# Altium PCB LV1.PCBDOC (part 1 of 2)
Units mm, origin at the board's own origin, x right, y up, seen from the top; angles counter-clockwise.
Board outline 220.06 x 100 mm, 2 copper layers (Component Side, Bottom Layer), stack 0.325 mm thick; 185 components, 114 nets, 661 pads, 212 vias.
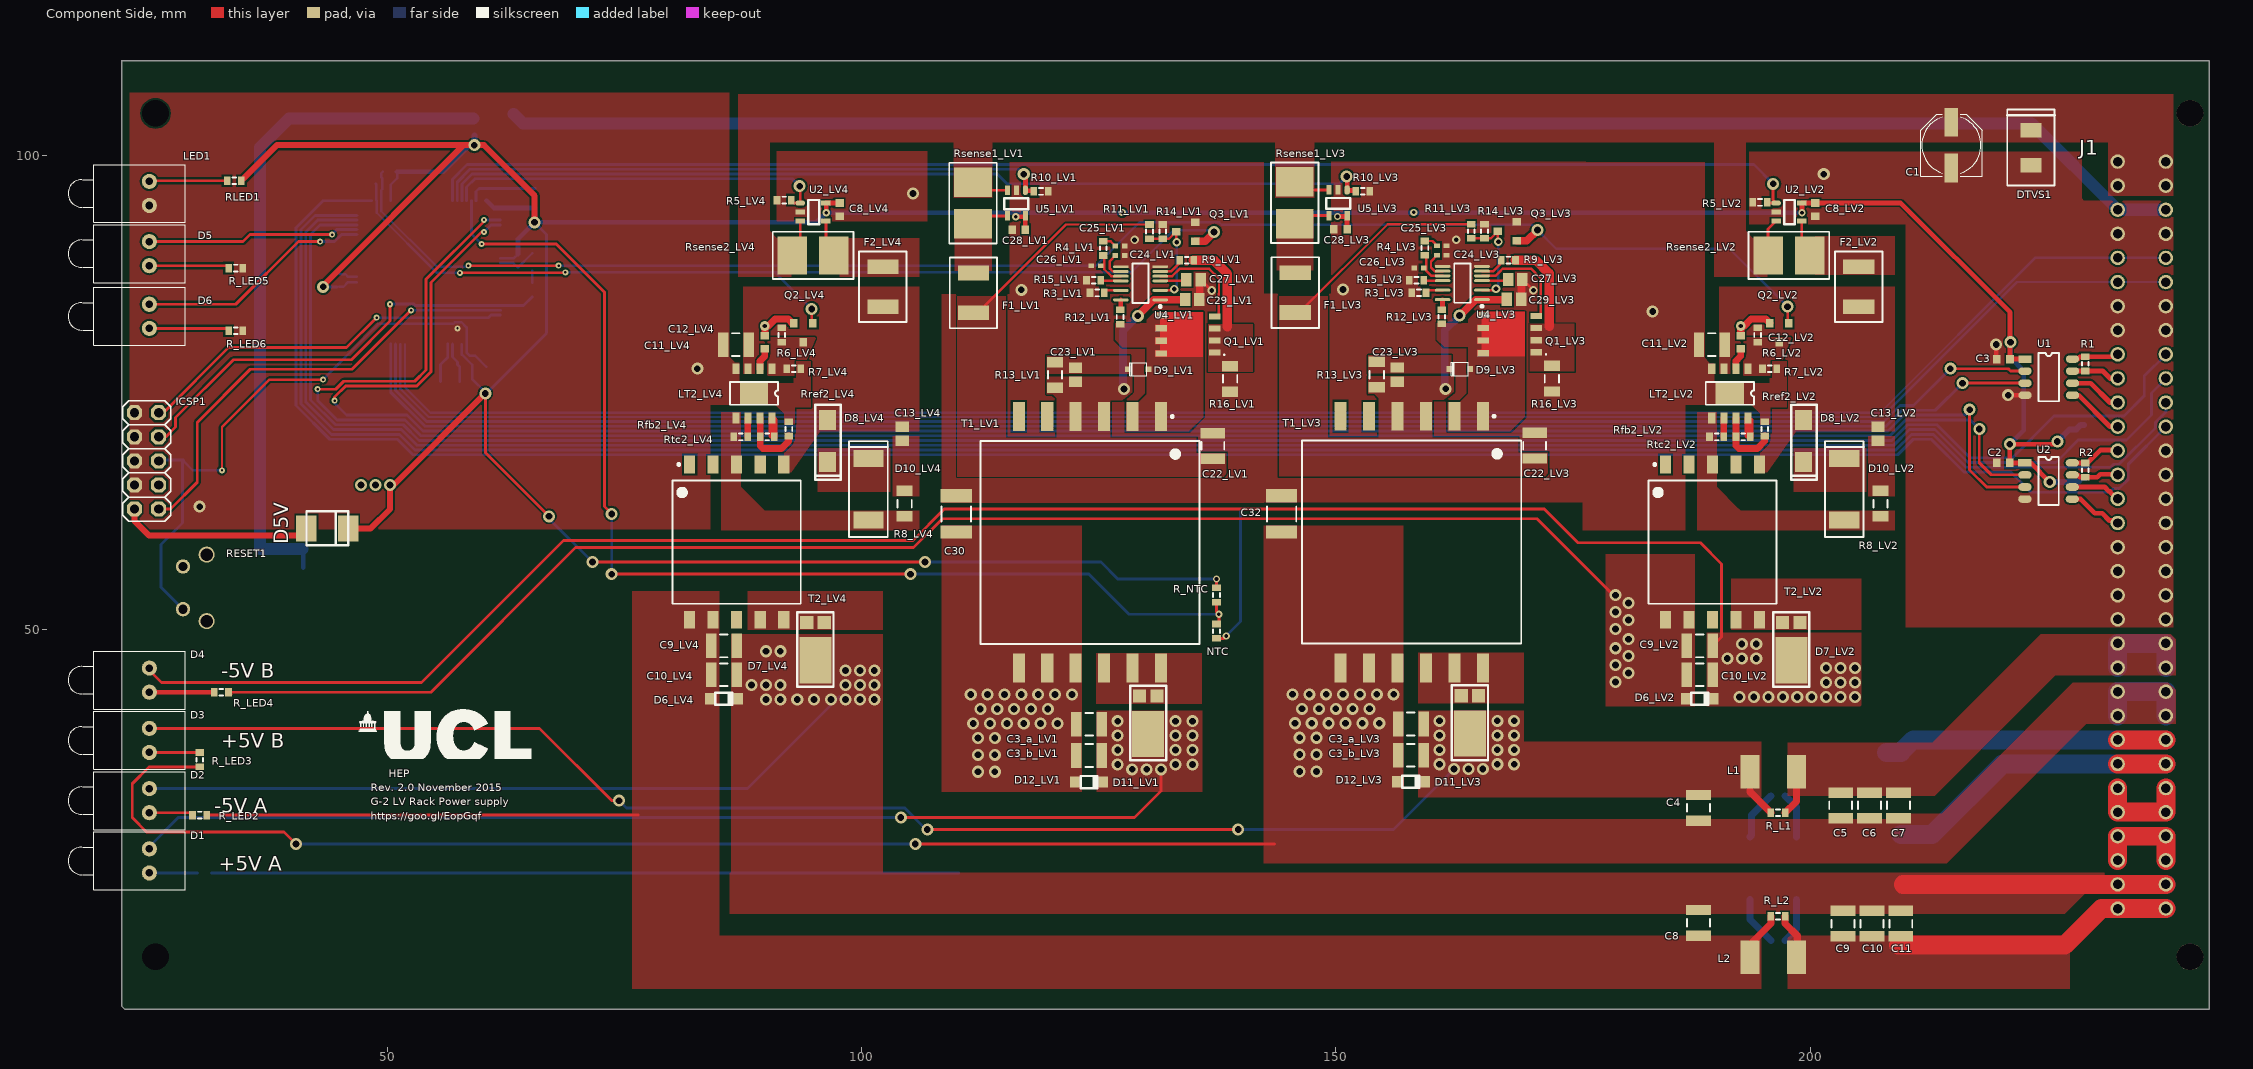
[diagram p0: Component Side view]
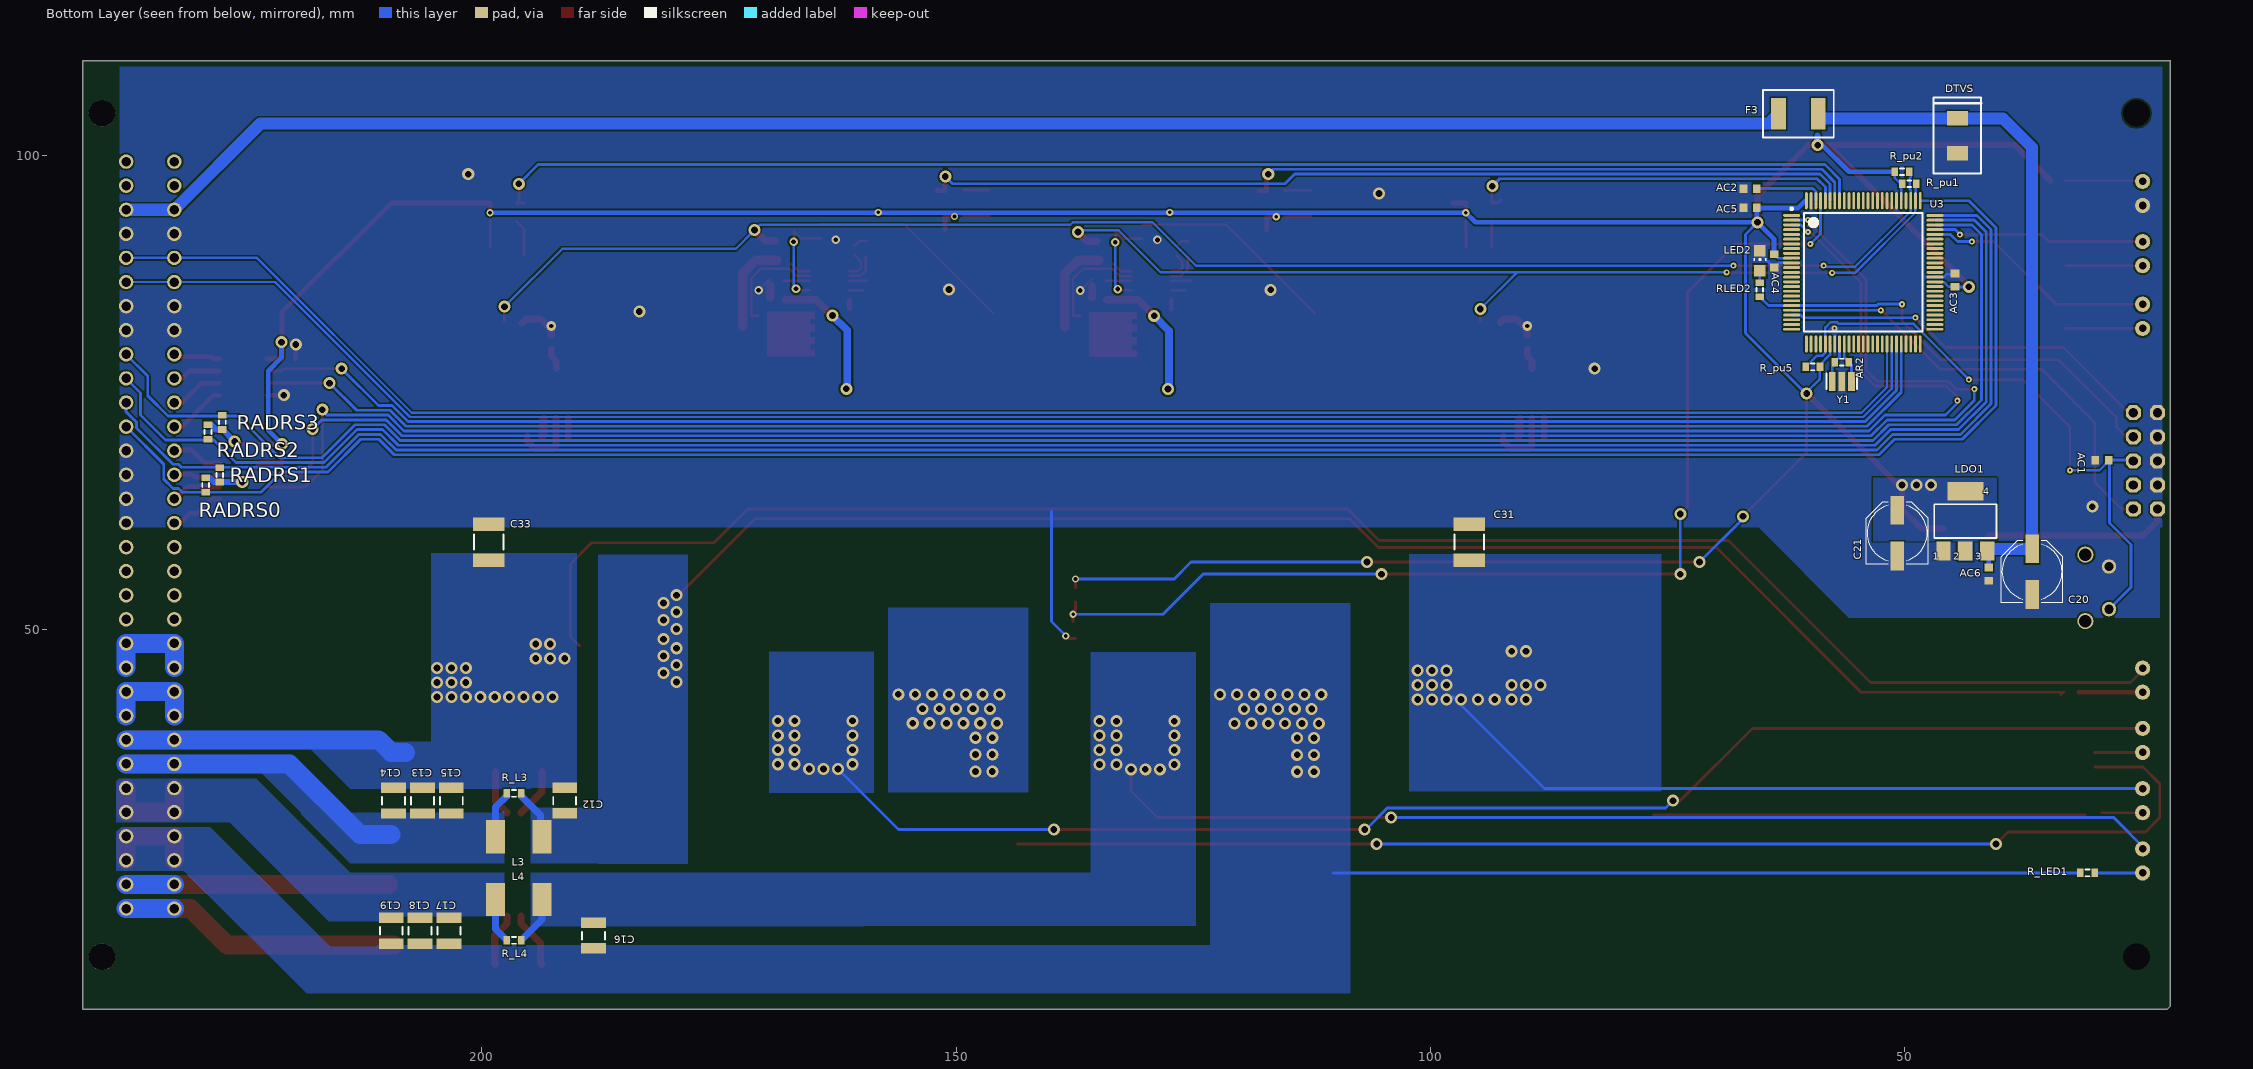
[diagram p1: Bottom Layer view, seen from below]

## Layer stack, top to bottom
Top Solder: solder mask 0.0102, Solder Resist, Dk 3.5
Component Side: signal copper 0.0356
Dielectric 1: core 0.254, FR-4, Dk 4.2
Bottom Layer: signal copper 0.0356
Solder Side: solder mask 0.0102, Solder Resist, Dk 3.5

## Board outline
242.062,110 22.018,110 22,109.982 22,10.414 22,10.352 22.352,10 242.062,10

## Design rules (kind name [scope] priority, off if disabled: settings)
Clearance [InNamedPolygon('GNDtop')] p1: gap=0.2
Clearance Clearance_2 [InNamedPolygon('GNDbottom')] p2: gap=0.2
Clearance Clearance_1 [All] p3: gap=0.2
FabricationTestPointUsage TestPointUsage [All] p1: valid=0 allowmultiple=FALSE
FabricationTestpoint Testpoint [All] p1: side=3 testpointundercomponent=TRUE minsize=1.016 maxsize=2.54 preferedsize=1.524 minholesize=0.508 maxholesize=1.016 preferedholesize=0.813 testpointgrid=0.025 allowsidetop=TRUE allowsidebottom=TRUE usegrid=TRUE gridtolerance=0
PlaneClearance [All] p1: clearance=0.254
PolygonConnect [All] p1: connectstyle=Direct reliefconductorwidth=0.254 reliefentries=4 polygonreliefangle="90 Angle" airgapwidth=0.254
RoomDefinition LV3 [InComponentClass('LV3')] p1: confinementstyle=ConfineIn formatcopy=TRUE lockcomponents=FALSE outline 141.09,32.032 177.158,32.032 177.158,103.152 141.09,103.152
RoomDefinition U_controller [InComponentClass('U_controller')] p2: confinementstyle=ConfineIn formatcopy=TRUE lockcomponents=FALSE outline 93.98,48.768 93.98,110.998 13.716,110.998 13.716,48.768
RoutingVias [All] p1: holewidth=0.254 width=0.508 viastyle="Through Hole" minholewidth=0.254 minwidth=0.508 maxholewidth=0.711 maxwidth=1.27
SilkToSolderMaskClearance SilkscreenOverComponentPads [IsPad] p1: minsilkscreentomaskgap=0.254 clearancetoexposedcopper=TRUE
SolderMaskExpansion [All] p1: expansion=0.051
Width Width_1 [InNet('ISENSE_2') OR InNet('ISENSE_1') OR InNet('NEGISENSE_2') OR InNet('NEGISENSE_1') OR InNet('L_OUT+') OR InNet('L_OUT-') OR InNet('NEGL_OUT+') OR InNet('NEGL_OUT-') OR InNet('SW')] p1: maxlimit=2 minlimit=0.254 preferedwidth=1 minimp=50.000000 maximp=50.000000 favimp=50.000000
Width [All] p2: maxlimit=2 minlimit=0.254 preferedwidth=0.254 minimp=50.000000 maximp=50.000000 favimp=50.000000
26 further rules are at their usual default settings.

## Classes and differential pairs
net class ADRS[0..3]: ADRS0 ADRS1 ADRS2 ADRS3
component class Top: *1 C1 C2 C3 C4 C5 C6 C7 C8 C9 C10 C11 C12 C13 C14 C15 C16 C17 C18 C19 C30 C31 C32 C33 C34 C35 C36 C37 C38 C39 C40 C41 C42 C43 C44 C45 D1 D2 D3 D4 D5 D6 DTVS1 J1 L1 L2 L3 L4 NTC NTC1 R1 R2 R19 R20 R_L1 R_L2 R_L3 R_L4 R_LED1 R_LED2 R_LED3 R_LED4 R_LED5 R_LED6 R_NTC R_NTC1 RADRS0 RADRS1 RADRS2 RADRS3 RADRS4 U1 U2 U6
channel class LV1: LV1 LV2 LV3 LV4
component class LV4: C8_LV4 C9_LV4 C10_LV4 C11_LV4 C12_LV4 C13_LV4 C34 D6_LV4 D7 D7_LV4 D8 D8_LV4 D10 D10_LV4 D13 F2_LV4 LT1 LT2_LV4 Q2_LV4 R5_LV4 R6_LV4 R7 R7_LV4 R8_LV4 Rfb1 Rfb2_LV4 Rref1 Rref2_LV4 Rsense2 Rsense2_LV4 Rtc1 Rtc2_LV4 T2_LV4 U2_LV4 U6
component class LV2: C8_LV2 C9_LV2 C10_LV2 C11_LV2 C12_LV2 C13_LV2 C36 C44 C46 C47 D6_LV2 D7_LV2 D8_LV2 D10_LV2 D14 D15 D16 D17 F2_LV2 LT2 LT2_LV2 Q2_LV2 Q4 R5_LV2 R6_LV2 R7_LV2 R8 R8_LV2 R17 R18 Rfb2 Rfb2_LV2 Rref2 Rref2_LV2 Rsense2_LV2 Rsense3 Rtc2 Rtc2_LV2 T2_LV2 T3 U2_LV2
component class U_controller: AC1 AC2 AC3 AC4 AC5 AC6 AR1 AR2 C20 C21 C41 C46 C47 D5V DTVS DTVS2 F3 F4 ICSP1 LDO1 LED1 LED2 R_pu1 R_pu2 R_pu3 R_pu5 RESET1 RLED1 RLED2 U3 U7 Y1
component class LV1: C3_a_LV1 C3_b_LV1 C22_LV1 C23_LV1 C24_LV1 C25_LV1 C26_LV1 C27_LV1 C28_LV1 C29_LV1 C39 C40 C41 C43 C44 D9_LV1 D11_LV1 D12_LV1 D13 F1_LV1 F2 Q1_LV1 Q2 Q3_LV1 R3_LV1 R4_LV1 R5 R6 R7 R8 R9_LV1 R10_LV1 R11_LV1 R12_LV1 R13_LV1 R14_LV1 R15_LV1 R16_LV1 Rsense1_LV1 Rsense2 T1_LV1 T2 U4_LV1 U5_LV1
component class LV3: C3_a_LV3 C3_b_LV3 C22_LV3 C23_LV3 C24_LV3 C25_LV3 C26_LV3 C27_LV3 C28_LV3 C29_LV3 D9_LV3 D11_LV3 D12_LV3 F1_LV3 Q1_LV3 Q3_LV3 R3_LV3 R4_LV3 R9_LV3 R10_LV3 R11_LV3 R12_LV3 R13_LV3 R14_LV3 R15_LV3 R16_LV3 Rsense1_LV3 T1_LV3 U4_LV3 U5_LV3
channel class LV2: LV1 LV3

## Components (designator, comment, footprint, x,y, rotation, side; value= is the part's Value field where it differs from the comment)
AC1 "Cap Semi" 1608[0603] 29.21,67.898 r0 bottom
AC2 "Cap Semi" 1608[0603] 66.294,96.52 r180 bottom
AC3 "Cap Semi" 1608[0603] 44.704,86.868 r270 bottom
AC4 "Cap Semi" 1608[0603] 63.77,88.9 r90 bottom
AC5 "Cap Semi" 1608[0603] 66.294,94.488 r180 bottom
AC6 "Cap Semi" 1608[0603] 41.148,55.88 r90 bottom
AR2 "" J1-0603 56.642,78.232 r0 bottom
C1 "" PANASONIC_D 214.884,101.092 r90 top
C2 "Cap Semi" 1608[0603] 220.338,67.605 r0 top
C3 "Cap Semi" 1608[0603] 220.358,78.55 r0 top
C3_a_LV1 "Cap Semi" C1210 123.984,40.063 r0 top (schematic designator C3_a)
C3_a_LV3 "Cap Semi" C1210 157.9,40.091 r0 top (schematic designator C3_a)
C3_b_LV1 "Cap Semi" C1210 123.984,36.761 r0 top (schematic designator C3_b)
C3_b_LV3 "Cap Semi" C1210 157.9,36.789 r0 top (schematic designator C3_b)
C4 "Cap Semi" C1210 188.214,31.25 r90 top
C5 "Cap Semi" C1210 203.2,31.496 r90 top
C6 "Cap Semi" C1210 206.248,31.496 r90 top
C7 "Cap Semi" C1210 209.296,31.496 r90 top
C8 "Cap Semi" C1210 188.214,19.13 r90 top
C8_LV2 "Cap Semi" 1608[0603] 200.546,94.298 r90 top (schematic designator C8)
C8_LV4 "Cap Semi" 1608[0603] 97.676,94.298 r90 top (schematic designator C8)
C9 "Cap Semi" C1210 203.454,19.05 r90 top
C9_LV2 "Cap Semi" C1210 188.354,48.324 r0 top (schematic designator C9)
C9_LV4 "Cap Semi" C1210 85.484,48.324 r0 top (schematic designator C9)
C10 "Cap Semi" C1210 206.502,19.05 r90 top
C10_LV2 "Cap Semi" C1210 188.354,45.276 r0 top (schematic designator C10)
C10_LV4 "Cap Semi" C1210 85.484,45.276 r0 top (schematic designator C10)
C11 "Cap Semi" C1210 209.55,19.05 r90 top
C11_LV2 "Cap Semi" C1210 189.624,80.074 r0 top (schematic designator C11)
C11_LV4 "Cap Semi" C1210 86.754,80.074 r0 top (schematic designator C11)
C12 "Cap Semi" C1210 191.262,32.004 r270 bottom
C12_LV2 "Cap Semi" 1608[0603] 192.672,80.328 r90 top (schematic designator C12)
C12_LV4 "Cap Semi" 1608[0603] 89.802,80.328 r90 top (schematic designator C12)
C13 "Cap Semi" C1210 206.248,31.996 r270 bottom
C13_LV2 "Cap Semi" C0805 207.15,70.676 r90 top (schematic designator C13)
C13_LV4 "Cap Semi" C0805 104.28,70.676 r90 top (schematic designator C13)
C14 "Cap Semi" C1210 209.296,31.996 r270 bottom
C15 "Cap Semi" C1210 203.2,31.996 r270 bottom
C16 "Cap Semi" C1210 188.214,17.78 r270 bottom
C17 "Cap Semi" C1210 203.446,18.288 r270 bottom
C18 "Cap Semi" C1210 206.502,18.288 r270 bottom
C19 "Cap Semi" C1210 209.542,18.288 r270 bottom
C20 "" PANASONIC_D 36.576,56.134 r90 bottom
C21 "" PANASONIC_D 50.8,60.198 r90 bottom
C22_LV1 "Cap Semi" C1210 137.026,69.394 r270 top (schematic designator C22)
C22_LV3 "Cap Semi" C1210 170.942,69.422 r270 top (schematic designator C22)
C23_LV1 "Cap Semi" C0805 122.548,76.887 r270 top (schematic designator C23)
C23_LV3 "Cap Semi" C0805 156.464,76.915 r270 top (schematic designator C23)
C24_LV1 "Cap Semi" 0402 127.247,89.46 r180 top (schematic designator C24)
C24_LV3 "Cap Semi" 0402 161.163,89.488 r180 top (schematic designator C24)
C25_LV1 "Cap Semi" 0402 127.247,90.476 r180 top (schematic designator C25)
C25_LV3 "Cap Semi" 0402 161.163,90.504 r180 top (schematic designator C25)
C26_LV1 "Cap Semi" 0402 124.714,88.392 r0 top (schematic designator C26)
C26_LV3 "Cap Semi" 0402 158.75,88.138 r0 top (schematic designator C26)
C27_LV1 "Cap Semi" C0805 134.994,86.92 r180 top (schematic designator C27)
C27_LV3 "Cap Semi" C0805 168.91,86.948 r180 top (schematic designator C27)
C28_LV1 "Cap Semi" 1608[0603] 116.572,92.202 r0 top (schematic designator C28)
C28_LV3 "Cap Semi" 1608[0603] 150.488,92.23 r0 top (schematic designator C28)
C29_LV1 "Cap Semi" C0805 134.86,84.836 r180 top (schematic designator C29)
C29_LV3 "Cap Semi" C0805 168.776,84.864 r180 top (schematic designator C29)
C30 "Cap Semi" 1812 109.982,62.23 r270 top
C31 "Cap Semi" 1812 95.898,59.246 r270 bottom
C32 "Cap Semi" 1812 144.272,62.23 r270 top
C33 "Cap Semi" 1812 199.276,59.246 r270 bottom
D1 "LEDGREEN" LEDGREEN 24.924,25.654 r180 top
D2 "LEDGREEN" LEDGREEN 24.924,32.004 r180 top
D3 "LEDGREEN" LEDGREEN 24.924,38.354 r180 top
D4 "LEDGREEN" LEDGREEN 24.924,44.704 r180 top
D5 "LEDYELLOW" LEDYELLOW 24.924,89.662 r180 top
D5V "MBRS130LT3G" SMB-403A 43.688,60.706 r180 top
D6 "LEDYELLOW" LEDYELLOW 24.924,83.058 r180 top
D6_LV2 "BZT52H-B5V6" SOD123F 188.354,42.736 r180 top (schematic designator D6)
D6_LV4 "BZT52H-B5V6" SOD123F 85.484,42.736 r180 top (schematic designator D6)
D7_LV2 "PDS1040L" PDS1040L 198.006,46.8 r180 top (schematic designator D7)
D7_LV4 "PDS1040L" PDS1040L 95.136,46.8 r180 top (schematic designator D7)
D8_LV2 "SMAJ30A" DO-214AC 199.276,69.914 r90 top (schematic designator D8)
D8_LV4 "SMAJ30A" DO-214AC 96.406,69.914 r90 top (schematic designator D8)
D9_LV1 "BAV20WS" SOD-323 129.151,77.476 r0 top (schematic designator D9)
D9_LV3 "BAV20WS" SOD-323 163.067,77.504 r0 top (schematic designator D9)
D10_LV2 "ES3B" DO-214AB 203.594,64.834 r270 top (schematic designator D10)
D10_LV4 "ES3B" DO-214AB 100.724,64.834 r270 top (schematic designator D10)
D11_LV1 "PDS760-13" PDS1040L 130.207,39.047 r180 top (schematic designator D11)
D11_LV3 "PDS760-13" PDS1040L 164.123,39.075 r180 top (schematic designator D11)
D12_LV1 "BZT52H-B5V6" SOD123F 123.984,33.967 r180 top (schematic designator D12)
D12_LV3 "BZT52H-B5V6" SOD123F 157.9,33.995 r180 top (schematic designator D12)
DTVS "SMBJ10CA" DO-214AA 44.45,102.108 r270 bottom
DTVS1 "SMBJ48A" DO-214AA 223.266,100.838 r270 top
F1_LV1 "MINISMDC050F-2" MF-MSMF1 111.792,85.529 r270 top (schematic designator F1)
F1_LV3 "MINISMDC050F-2" MF-MSMF1 145.708,85.557 r270 top (schematic designator F1)
F2_LV2 "MINISMDC050F-2" MF-MSMF1 205.118,86.17 r270 top (schematic designator F2)
F2_LV4 "MINISMDC050F-2" MF-MSMF1 102.248,86.17 r270 top (schematic designator F2)
F3 "MINISMDC050F-2" MF-MSMF1 61.214,104.394 r180 bottom
ICSP1 "5x2 M" 2X05 24.638,67.818 r90 top
J1 "DIN41612_64WAY" "09 03 164 6919" 234.95,60 r270 top
L1 "Inductor" MPLC0730 196.088,35.052 r0 top
L2 "Inductor" MPLC0730 196.088,15.494 r0 top
L3 "Inductor" MPLC0730 196.088,28.194 r0 bottom
L4 "Inductor" MPLC0730 196.088,21.59 r0 bottom
LDO1 "LDO_5V" SOT223 43.614,61.468 r180 bottom
LED1 "LEDRED" LEDRED 24.924,96.012 r180 top
LED2 "GREEN" CHIP-LED0805 65.278,88.9 r180 bottom
LT2_LV2 "LT8302" S8E 193.434,77.534 r270 top (schematic designator LT2)
LT2_LV4 "LT8302" S8E 90.564,77.534 r270 top (schematic designator LT2)
NTC "" J1-0603 137.414,49.872 r90 top
Q1_LV1 "BSC320N20NS3 G" INF-PG-TDSON-8-1_V 134.391,81.146 r90 top (schematic designator Q1)
Q1_LV3 "BSC320N20NS3 G" INF-PG-TDSON-8-1_V 168.307,81.174 r90 top (schematic designator Q1)
Q2_LV2 "BSS131" SOT-23_2 196.736,81.344 r90 top (schematic designator Q2)
Q2_LV4 "BSS131" SOT-23_2 93.866,81.344 r90 top (schematic designator Q2)
Q3_LV1 "BSS131" SOT-23_2 134.16,91.99 r0 top (schematic designator Q3)
Q3_LV3 "BSS131" SOT-23_2 168.076,92.018 r0 top (schematic designator Q3)
R1 "" J1-0603 228.994,78.042 r90 top
R2 "" J1-0603 228.974,66.843 r270 top
R3_LV1 "Res3" J1-0603 124.834,85.523 r180 top (schematic designator R3)
R3_LV3 "Res3" J1-0603 158.75,85.551 r180 top (schematic designator R3)
R4_LV1 "Res3" J1-0603 125.469,90.222 r270 top (schematic designator R4)
R4_LV3 "Res3" J1-0603 159.385,90.25 r270 top (schematic designator R4)
R5_LV2 "Res3" J1-0603 194.704,95.06 r0 top (schematic designator R5)
R5_LV4 "Res3" J1-0603 91.834,95.314 r0 top (schematic designator R5)
R6_LV2 "Res3" J1-0603 194.45,81.09 r90 top (schematic designator R6)
R6_LV4 "Res3" J1-0603 91.58,81.09 r90 top (schematic designator R6)
R7_LV2 "Res3" J1-0603 195.72,77.534 r180 top (schematic designator R7)
R7_LV4 "Res3" J1-0603 92.85,77.534 r180 top (schematic designator R7)
R8_LV2 "Res3" C1206 207.404,63.31 r90 top (schematic designator R8)
R8_LV4 "Res3" C1206 104.534,63.31 r90 top (schematic designator R8)
R9_LV1 "Res3" J1-0603 134.271,88.958 r180 top (schematic designator R9)
R9_LV3 "Res3" J1-0603 168.187,88.986 r180 top (schematic designator R9)
R10_LV1 "Res3" J1-0603 118.916,96.22 r180 top (schematic designator R10)
R10_LV3 "Res3" J1-0603 152.832,96.248 r180 top (schematic designator R10)
R11_LV1 "Res3" J1-0603 130.35,91.99 r90 top (schematic designator R11)
R11_LV3 "Res3" J1-0603 164.266,92.018 r90 top (schematic designator R11)
R12_LV1 "Res3" J1-0603 127.247,82.983 r270 top (schematic designator R12)
R12_LV3 "Res3" J1-0603 161.163,83.011 r270 top (schematic designator R12)
R13_LV1 "Res3" C1206 120.389,76.887 r90 top (schematic designator R13)
R13_LV3 "Res3" C1206 154.305,76.915 r90 top (schematic designator R13)
R14_LV1 "Res3" J1-0603 131.747,91.99 r270 top (schematic designator R14)
R14_LV3 "Res3" J1-0603 165.663,92.018 r270 top (schematic designator R14)
R15_LV1 "Res3" J1-0603 124.46,86.868 r0 top (schematic designator R15)
R15_LV3 "Res3" J1-0603 158.496,86.868 r0 top (schematic designator R15)
R16_LV1 "Res3" C1206 138.851,76.456 r90 top (schematic designator R16)
R16_LV3 "Res3" C1206 172.767,76.484 r90 top (schematic designator R16)
R_L1 "Res3" J1-0603 196.596,30.734 r180 top
R_L2 "Res3" J1-0603 196.596,19.812 r180 top
R_L3 "Res3" J1-0603 196.596,32.766 r0 bottom
R_L4 "Res3" J1-0603 196.596,17.272 r0 bottom
R_LED1 "Res3" J1-0603 30.734,24.384 r0 bottom
R_LED2 "Res3" J1-0603 30.226,30.48 r0 top
R_LED3 "Res3" J1-0603 30.226,36.322 r270 top
R_LED4 "Res3" J1-0603 32.512,43.434 r0 top
R_LED5 "Res3" J1-0603 34.036,88.138 r0 top
R_LED6 "Res3" J1-0603 34.036,81.534 r0 top
R_NTC "" J1-0603 137.414,53.682 r90 top
R_pu1 "pullup" J1-0603 49.53,97.028 r180 bottom
R_pu2 "pullup" J1-0603 50.292,98.298 r180 bottom
R_pu5 "pullup" J1-0603 59.69,77.724 r180 bottom
RADRS0 "Res3" J1-0603 229.108,65.278 r270 bottom
RADRS1 "Res3" J1-0603 227.624,66.335 r90 bottom
RADRS2 "Res3" J1-0603 228.854,70.866 r270 bottom
RADRS3 "Res3" J1-0603 227.33,71.882 r90 bottom
RESET1 "PB_RST" 1-1825027-4 29.718,54.436 r270 top
Rfb2_LV2 "Res3" J1-0603 190.132,70.339 r180 top (schematic designator Rfb2)
Rfb2_LV4 "Res3" J1-0603 87.262,70.339 r180 top (schematic designator Rfb2)
RLED1 "" J1-0603 33.87,97.344 r180 top
RLED2 "" J1-0603 65.278,85.852 r270 bottom
Rref2_LV2 "Res3" J1-0603 195.212,71.184 r90 top (schematic designator Rref2)
Rref2_LV4 "Res3" J1-0603 92.342,71.184 r90 top (schematic designator Rref2)
Rsense1_LV1 "Rsense" R6432 111.746,94.996 r270 top (schematic designator Rsense1)
Rsense1_LV3 "Rsense" R6432 145.662,95.024 r270 top (schematic designator Rsense1)
Rsense2_LV2 "Rsense" R6432 197.752,89.472 r0 top (schematic designator Rsense2)
Rsense2_LV4 "Rsense" R6432 94.882,89.472 r0 top (schematic designator Rsense2)
Rtc2_LV2 "Res3" J1-0603 192.926,70.339 r180 top (schematic designator Rtc2)
Rtc2_LV4 "Res3" J1-0603 90.056,70.339 r180 top (schematic designator Rtc2)
T1_LV1 "750311597" EFD20 124.072,59.234 r270 top (schematic designator T1)
T1_LV3 "750311597" EFD20 157.988,59.262 r270 top (schematic designator T1)
T2_LV2 "36V" EP13 189.704,59.258 r90 top (schematic designator T2)
T2_LV4 "36V" EP13 86.834,59.258 r90 top (schematic designator T2)
U1 "ADM4855ARZ" SOICN8 222.644,78.55 r0 top
U2 "ADM4855ARZ" SOICN8 222.624,67.605 r0 top
U2_LV2 "INA138" SOT-23 197.752,94.044 r270 top (schematic designator U2)
U2_LV4 "INA138" SOT-23 94.882,94.044 r270 top (schematic designator U2)
U3 "ATmega2560-16AU" 100A_N 54.372,87.692 r180 bottom
U4_LV1 "LT3748IMS#PBF" LT-MS-16-4PR_N 129.406,86.539 r180 top (schematic designator U4)
U4_LV3 "LT3748IMS#PBF" LT-MS-16-4PR_N 163.322,86.567 r180 top (schematic designator U4)
U5_LV1 "INA138" SOT-23 116.318,94.996 r180 top (schematic designator U5)
U5_LV3 "INA138" SOT-23 150.234,95.024 r180 top (schematic designator U5)
Y1 "" RESONATOR 56.642,76.2 r180 bottom

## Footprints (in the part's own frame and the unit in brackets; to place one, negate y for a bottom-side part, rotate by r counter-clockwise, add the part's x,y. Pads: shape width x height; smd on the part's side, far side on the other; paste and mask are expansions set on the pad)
1-1825027-4 [mm]
  round 1.7 hole 1.3: 0(-3.505,1.245) 0(3.505,1.245)
  round 1.524 hole 0.99: 1(-2.25,-1.245) 2(2.25,-1.245)
  body extent -4.2,-7.37 4.2,2.78, height 7
2X05 [mil]
  oct 62x62 hole 38: 1(-200,-50) 2(-200,50) 3(-100,-50) 4(-100,50) 5(0,-50) 6(0,50) 7(100,-50) 8(100,50) 9(200,-50) 10(200,50)
  silkscreen extent -250,-100 250,100
"09 03 164 6919" [mil]
  round 110.24 hole 110.24: 0(-1750,200) 0(1750,200)
  round 60 hole 39.37: 0(-1550,100) 1(-1450,100) 2(-1350,100) 3(-1250,100) 4(-1150,100) 5(-1050,100) 6(-950,100) 7(-850,100) 8(-750,100) 9(-650,100) 10(-550,100) 11(-450,100) 12(-350,100) 13(-250,100) 14(-150,100) 15(-50,100) 16(50,100) 17(150,100) 18(250,100) 19(350,100) 20(450,100) 21(550,100) 22(650,100) 23(750,100) 24(850,100) 25(950,100) 26(1050,100) 27(1150,100) 28(1250,100) 29(1350,100) 30(1450,100) 31(1550,100) 32(-1550,-100) 33(-1450,-100) 34(-1350,-100) 35(-1250,-100) 36(-1150,-100) 37(-1050,-100) 38(-950,-100) 39(-850,-100) 40(-750,-100) 41(-650,-100) 42(-550,-100) 43(-450,-100) 44(-350,-100) 45(-250,-100) 46(-150,-100) 47(-50,-100) 48(50,-100) 49(150,-100) 50(250,-100) 51(350,-100) 52(450,-100) 53(550,-100) 54(650,-100) 55(750,-100) 56(850,-100) 57(950,-100) 58(1050,-100) 59(1150,-100) 60(1250,-100) 61(1350,-100) 62(1450,-100) 63(1550,-100)
  body extent -1850,-100 1851,609, height 368
100A_N [mm] "Thin QFP, 100-Leads, Body 14x14mm, Pitch 0.5mm, IPC Medium Density"
  oval 1.8x0.3 smd: 1(-7.55,6) 2(-7.55,5.5) 3(-7.55,5) 4(-7.55,4.5) 5(-7.55,4) 6(-7.55,3.5) 7(-7.55,3) 8(-7.55,2.5) 9(-7.55,2) 10(-7.55,1.5) 11(-7.55,1) 12(-7.55,0.5) 13(-7.55,0) 14(-7.55,-0.5) 15(-7.55,-1) 16(-7.55,-1.5) 17(-7.55,-2) 18(-7.55,-2.5) 19(-7.55,-3) 20(-7.55,-3.5) 21(-7.55,-4) 22(-7.55,-4.5) 23(-7.55,-5) 24(-7.55,-5.5) 25(-7.55,-6) 51(7.55,-6) 52(7.55,-5.5) 53(7.55,-5) 54(7.55,-4.5) 55(7.55,-4) 56(7.55,-3.5) 57(7.55,-3) 58(7.55,-2.5) 59(7.55,-2) 60(7.55,-1.5) 61(7.55,-1) 62(7.55,-0.5) 63(7.55,0) 64(7.55,0.5) 65(7.55,1) 66(7.55,1.5) 67(7.55,2) 68(7.55,2.5) 69(7.55,3) 70(7.55,3.5) 71(7.55,4) 72(7.55,4.5) 73(7.55,5) 74(7.55,5.5) 75(7.55,6)
  oval 0.3x1.8 smd: 26(-6,-7.55) 27(-5.5,-7.55) 28(-5,-7.55) 29(-4.5,-7.55) 30(-4,-7.55) 31(-3.5,-7.55) 32(-3,-7.55) 33(-2.5,-7.55) 34(-2,-7.55) 35(-1.5,-7.55) 36(-1,-7.55) 37(-0.5,-7.55) 38(0,-7.55) 39(0.5,-7.55) 40(1,-7.55) 41(1.5,-7.55) 42(2,-7.55) 43(2.5,-7.55) 44(3,-7.55) 45(3.5,-7.55) 46(4,-7.55) 47(4.5,-7.55) 48(5,-7.55) 49(5.5,-7.55) 50(6,-7.55) 76(6,7.55) 77(5.5,7.55) 78(5,7.55) 79(4.5,7.55) 80(4,7.55) 81(3.5,7.55) 82(3,7.55) 83(2.5,7.55) 84(2,7.55) 85(1.5,7.55) 86(1,7.55) 87(0.5,7.55) 88(0,7.55) 89(-0.5,7.55) 90(-1,7.55) 91(-1.5,7.55) 92(-2,7.55) 93(-2.5,7.55) 94(-3,7.55) 95(-3.5,7.55) 96(-4,7.55) 97(-4.5,7.55) 98(-5,7.55) 99(-5.5,7.55) 100(-6,7.55)
  silkscreen extent -7.68,-6.25 6.25,6.82, body extent -7,-7 7,7, height 1.2
0402 [mm] "Chip Capacitor, Body 1.0x0.5mm, IPC High Density"
  rect 0.6x0.5 smd: 1(-0.5,0) 2(0.5,0)
  body extent -0.55,-0.3 0.55,0.3, height 1.3
1608[0603] [mm] "Chip Capacitor, Body 1.6x0.8mm, IPC High Density"
  rect 0.8x0.9 smd: 1(-0.7,0) 2(0.7,0)
  body extent -0.87,-0.48 0.87,0.48, height 1.3
1812 [mm] "Chip Capacitor, Body 4.5x3.2mm, IPC High Density"
  rect 1.4x3.3 smd: 1(-1.9,0) 2(1.9,0)
  silkscreen extent -0.8,-1.55 0.8,1.55, body extent -2.4,-1.7 2.4,1.7, height 1.4
C0805 [mm] "Chip Capacitor, Body 2.0x1.3mm, IPC High Density"
  rect 1.1x1.4 smd: 1(-0.75,0) 2(0.75,0)
  body extent -1.1,-0.72 1.1,0.72, height 1.4
C1206 [mm] "Chip Capacitor, Body 3.2x1.6mm, IPC High Density"
  rect 1.1x1.7 smd: 1(-1.35,0) 2(1.35,0)
  silkscreen extent -0.4,-0.75 0.4,0.75, body extent -1.7,-0.9 1.7,0.9, height 1.3
C1210 [mm] "Chip Capacitor, Body 3.2x2.5mm, IPC High Density"
  rect 1.1x2.6 smd: 1(-1.35,0) 2(1.35,0)
  silkscreen extent -0.4,-1.2 0.4,1.2, body extent -1.7,-1.35 1.7,1.35, height 1.3
CHIP-LED0805 [mil]
  rect 48x48 smd: A(0,-41.34) C(0,42)
  silkscreen extent -27,0 27,12
DO-214AA [mm]
  rect 1.52x2.18 smd: 1(-1.84,0) 2(1.84,0)
  silkscreen extent -4.01,-2.5 4.01,2.5
DO-214AB [mm]
  rect 1.8x3.2 smd: 1(-3.25,0) 2(3.25,0)
  silkscreen extent -5.05,-2.03 5.05,2.03
DO-214AC [mm]
  rect 2.1x1.8 smd: 1(2.2,0) 2(-2.2,0)
  silkscreen extent -4.06,-1.4 3.81,1.27
EFD20 [mm] "SMD, 10-Leads, Body 22.0x20.0mm (max), Pitch 3.75mm, IPC Medium Density"
  rect 3.05x1.27 smd: 1(-13.26,7.5) 2(-13.26,4.5) 3(-13.26,1.5) 4(-13.26,-1.5) 5(-13.26,-4.5) 6(-13.26,-7.5) 7(13.26,-7.5) 8(13.26,-4.5) 9(13.26,-1.5) 10(13.26,1.5) 11(13.26,4.5) 12(13.26,7.5)
  silkscreen extent -13.38,-11.55 10.7,11.55, body extent -14.54,-10 14.54,10, height 11.43
EP13 [mm] "SMD, 10-Leads, Body 13.5x14.0mm (max), Pitch 2.48mm, IPC Medium Density"
  rect 1.88x1.17 smd: 1(8.18,4.96) 2(8.18,2.48) 3(8.18,0) 4(8.18,-2.48) 5(8.18,-4.96) 6(-8.18,-4.96) 7(-8.18,-2.48) 8(-8.18,0) 9(-8.18,2.48) 10(-8.18,4.96)
  silkscreen extent -6.5,-6.75 8.3,6.75, body extent -8.88,-6.75 8.87,6.75, height 12.5
INF-PG-TDSON-8-1_V [mm] "TDSON, 8-Leads, Body 6.15x5.15mm, Pitch 1.27mm"
  rect 0.65x1.2 smd: 1(-1.905,-2.825) 2(-0.635,-2.825) 3(0.635,-2.825) 4(1.905,-2.825) 5(2.007,2.794) 6(0.66,2.794) 7(-0.66,2.794) 8(-2.007,2.794)
  Component Side region: 0.315,2.925 1.015,2.925 1.015,3.425 0.315,3.425
  Component Side region: -1.015,2.925 -0.315,2.925 -0.315,3.425 -1.015,3.425
  Component Side region: 1.65,2.925 2.35,2.925 2.35,3.425 1.65,3.425
  Component Side region: -2.35,2.925 -1.65,2.925 -1.65,3.425 -2.35,3.425
  Component Side region: -2.35,2.925 -2.35,-1.575 2.35,-1.575 2.35,2.925
  silkscreen extent -2.23,-3.94 -2.03,-3.74, body extent -2.58,-3.08 2.58,3.08, height 1
J1-0603 [mm] "Chip Resistor, Body 1.6x0.8mm, IPC High Density"
  rect 0.7x0.9 smd: 1(-0.75,0) 2(0.75,0)
  silkscreen extent -0.2,-0.35 0.2,0.35, body extent -0.85,-0.48 0.85,0.48, height 0.9
LEDGREEN [mm] "LED; 2 Leads"
  round 1.6 hole 0.8: 1(0,1.27) 2(0,-1.27)
  silkscreen extent -3.81,-3.05 8.56,3.05, body extent -3.76,-3.05 8.64,2.92, height 5.97
LEDRED [mm] "LED; 2 Leads"
  round 1.6 hole 0.8: 1(0,1.27) 2(0,-1.27)
  silkscreen extent -3.81,-3.05 8.56,3.05, body extent -3.76,-3.05 8.64,2.92, height 5.97
LEDYELLOW [mm] "LED; 2 Leads"
  round 1.6 hole 0.8: 1(0,1.27) 2(0,-1.27)
  silkscreen extent -3.81,-3.05 8.56,3.05, body extent -3.76,-3.05 8.64,2.92, height 5.97
LT-MS-16-4PR_N [mm] "SOP, 12-Leads, Body 4.1x3.1mm, Pitch 0.5mm, IPC Medium Density"
  oval 1.65x0.3 smd: 1(-2.075,1.75) 3(-2.075,0.75) 5(-2.075,-0.25) 6(-2.075,-0.75) 7(-2.075,-1.25) 8(-2.075,-1.75) 9(2.075,-1.75) 10(2.075,-1.25) 11(2.075,-0.75) 12(2.075,-0.25) 14(2.075,0.75) 16(2.075,1.75)
  silkscreen extent -2.2,-2.08 0.85,2.57, body extent -1.55,-2.05 1.55,2.05, height 1.1
MF-MSMF1 [mm]
  rect 1.55x3.3 smd: 1(-2.1,0) 2(2.1,0)
  silkscreen extent -3.73,-2.5 3.73,2.5
MPLC0730 [mm]
  rect 2x3.5 smd: 1(2.45,0) 2(-2.45,0)
  body extent -3.18,-2.67 3.17,2.79, height 2
PANASONIC_D [mil]
  rect 119x56 smd: 1(95,0) 2(-94.49,0)
  silkscreen extent -128,-128 128,128, body extent -130,-125 125,125, height 236
PDS1040L [mm]
  rect 1.39x1.4 smd: 1(-0.92,-3.982) 1(0.92,-3.982)
  rect 3.36x4.86 smd: 2(0,0)
  silkscreen extent -1.9,-5.08 1.91,2.79, body extent -1.52,-4.06 1.52,2.29, height 1
R6432 [mm]
  rect 3.1x4 smd: 1(-2.2,0) 2(2.2,0)
  silkscreen extent -4.25,-2.5 4.25,2.5
RESONATOR [mil]
  rect 28x79 smd: 1(-39.37,0) 2(0,0) 3(40,0)
  silkscreen extent -63,-31 63,32
S8E [mil]
  rect 45x30 smd: 1(0,0) 2(0,-50) 3(0,-100) 4(0,-150) 5(205,-150) 6(205,-100) 7(205,-50) 8(205,0)
  rect 89x118 smd: 4(102.5,-75)
  silkscreen extent 55,-175 149,25
SMB-403A [mm]
  rect 2.159x2.743 smd: 1(-2.21,0) 2(2.21,0)
  silkscreen extent -2.2,-1.8 2.2,1.8, body extent -2.1,-1.9 2.3,1.7, height 2
SOD123F [mm]
  rect 1.2x1.2 smd: 1(-1.4,0) 2(1.4,0)
  silkscreen extent -1.02,-0.63 0.89,0.64
SOD-323 [mm]
  rect 0.6x0.6 smd: 1(-1.1,0) 2(1.1,0)
  silkscreen extent -0.9,-0.7 0.9,0.7
SOICN8 [mm]
  rect 1.4x0.8 smd: 1(0,0)
  oval 1.4x0.8 smd: 2(0,-1.27) 3(0,-2.54) 4(0,-3.81) 5(5,-3.81) 6(5,-2.54) 7(5,-1.27) 8(5,0)
  silkscreen extent 1.43,-4.44 3.56,0.64, body extent -0.38,-4.7 5.46,0.89, height 1
SOT223 [mm]
  rect 1.5x2 smd: 1(-2.3,-3.15) 2(0,-3.15) 3(2.3,-3.15)
  rect 3.8x2 smd: 4(0,3.15)
  silkscreen extent -3.28,-1.78 3.28,1.78, body extent -3.3,-4.2 3.3,4.2, height 1
SOT-23 [mm]
  oval 0.55x1 smd: 1(-0.95,-1.35)
  rect 0.55x1 smd: 2(0,-1.35) 3(0.95,-1.35) 4(0.95,1.35) 5(-0.95,1.35)
  silkscreen extent -1.27,-0.51 1.27,0.63
SOT-23_2 [mm]
  rect 0.9x0.8 smd: 1(1,-1) 2(1,1) 3(-1,0)
  body extent -0.89,-1.02 1.02,1.14, height 0.5

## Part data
AC1 AC2 AC3 AC4 AC5 AC6 C2 C3 C3_a_LV1 C3_a_LV3 C3_b_LV1 C3_b_LV3 C4 C5 C6 C7 C8 C8_LV2 C8_LV4 C9 C9_LV2 C9_LV4 C10 C10_LV2 C10_LV4 C11 C11_LV2 C11_LV4 C12 C12_LV2 C12_LV4 C13 C13_LV2 C13_LV4 C14 C15 C16 C17 C18 C19 C22_LV1 C22_LV3 C23_LV1 C23_LV3 C24_LV1 C24_LV3 C25_LV1 C25_LV3 C26_LV1 C26_LV3 C27_LV1 C27_LV3 C28_LV1 C28_LV3 C29_LV1 C29_LV3 C30 C31 C32 C33: "Capacitor (Semiconductor SIM Model)"
AR2 NTC R1 R2 R_NTC R_pu1 R_pu2 R_pu5 RLED1 RLED2: library part Res3, "Resistor"
C1 C20 C21: library part CPOL-EUD
D5V D9_LV1 D9_LV3 D10_LV2 D10_LV4: "Power Diode"
D6_LV2 D6_LV4 D12_LV1 D12_LV3: "Zener Diode"
D7_LV2 D7_LV4: "Schottky Diode"
D8_LV2 D8_LV4: library part "D Zener", "Zener Diode"
D11_LV1 D11_LV3: library part PDS1040L, "Schottky Diode"
DTVS DTVS1: library part SMBJ, "TVS"
F1_LV1 F1_LV3 F2_LV2 F2_LV4 F3: library part "Fuse 1", "Fuse"
ICSP1: library part PINHD-2X5
LED2: library part LEDCHIP-LED0805
Q1_LV1 Q1_LV3: "N-Channel OptiMOS 3 Power-Transistor, 200 V VDS, 36 A ID, -55 to 150 degC, PG-TDSON-8-1, Reel, Green"
Q2_LV2 Q2_LV4 Q3_LV1 Q3_LV3: "N-Channel MOSFET"
R3_LV1 R3_LV3 R4_LV1 R4_LV3 R5_LV2 R5_LV4 R6_LV2 R6_LV4 R7_LV2 R7_LV4 R8_LV2 R8_LV4 R9_LV1 R9_LV3 R10_LV1 R10_LV3 R11_LV1 R11_LV3 R12_LV1 R12_LV3 R13_LV1 R13_LV3 R14_LV1 R14_LV3 R15_LV1 R15_LV3 R16_LV1 R16_LV3 R_L1 R_L2 R_L3 R_L4 R_LED1 R_LED2 R_LED3 R_LED4 R_LED5 R_LED6 RADRS0 RADRS1 RADRS2 RADRS3 Rfb2_LV2 Rfb2_LV4 Rref2_LV2 Rref2_LV4 Rtc2_LV2 Rtc2_LV4: "Resistor"
Rsense1_LV1 Rsense1_LV3 Rsense2_LV2 Rsense2_LV4: "CRF2512-FV-R001ELF"
T1_LV1 T1_LV3: "Flyback Transformer suitable or LT3573/ LT3574/ LT3575/ LT3748 WE-FB, Ui=20-48V"
T2_LV2 T2_LV4: library part "WE-FB, 750311457", "Flyback Transformer suitable or LT3573/ LT3574/ LT3575/ LT3748 WE-FB, Ui=36V"
U1 U2: library part SP3084EEN-L
U3: "8-bit AVR Microcontroller, 4.5-5.5V, 16MHz, 256KB Flash, 4KB EEPROM, 8KB SRAM, 86 GPIO pins, 100-pin TQFP, Industrial Grade (-40°C to 85°C), Pb-Free"
U4_LV1 U4_LV3: "Isolated Flyback Controller, 16-pin SOP (MS-16), -40 to 125 degC, Pb-Free"
Y1: library part RESONATORMU

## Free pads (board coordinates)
  round 2.6 hole 2.8: 2(25.57,15.549) 2(25.57,104.444)

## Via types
v1: diameter 1.27, hole 0.711, Component Side to Bottom Layer, 176 vias
v2: diameter 0.635, hole 0.254, Component Side to Bottom Layer, 17 vias
v3: diameter 0.762, hole 0.381, Component Side to Bottom Layer, 9 vias
v4: diameter 0.9, hole 0.5, Component Side to Bottom Layer, 8 vias
v5: diameter 1.016, hole 0.457, Component Side to Bottom Layer, 2 vias

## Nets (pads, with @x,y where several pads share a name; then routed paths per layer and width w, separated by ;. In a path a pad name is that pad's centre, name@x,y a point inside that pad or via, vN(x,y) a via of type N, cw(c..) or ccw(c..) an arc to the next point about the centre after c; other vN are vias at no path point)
48V: C1.1 DTVS1.1 J1.0@237.49,99.37 J1.1 J1.32 J1.33 Rsense1_LV1.1 Rsense1_LV3.1 Rsense2_LV2.1 Rsense2_LV4.1 U2_LV2.3 U2_LV4.3 U5_LV1.3 U5_LV3.3 | length 12.3
  Component Side w0.3: Rsense2_LV4.1@93.532,90.322 U2_LV4.3@93.532,93.094 ; Rsense1_LV1.1@112.596,96.346 U5_LV1.3@115.368,96.346 ; Rsense1_LV3.1@146.512,96.374 U5_LV3.3@149.284,96.374 ; Rsense2_LV2.1@195.552,89.472 195.552,92.244 U2_LV2.3@196.402,93.094
+5V: AC3.2 AC4.2 AC5.2 C2.2 C3.2 C8_LV2.2 C8_LV4.2 C21.1 C28_LV1.2 C28_LV3.2 D5V.1 LDO1.2 LDO1.4 R_NTC.2 R_pu1.1 R_pu2.1 R_pu5.2 RADRS0.1 RADRS1.1 RADRS2.1 RADRS3.1 RLED1.1 U1.1 U2.1 U2_LV2.5 U2_LV4.5 U3.10 U3.31 U3.61 U3.80 U3.100 U5_LV1.5 U5_LV3.5 | length 435.2
  Component Side w0.305: v1(60.338,74.932) 60.338,68.694 v1(67.056,61.976) ; v1(71.628,57.15) v1(106.68,57.15) ; v3(137.414,55.372) 137.414,54.456 R_NTC.2@137.426,54.444
  Component Side w0.5: U2_LV4.5@96.232,94.994 C8_LV4.2@97.672,94.994 ; v3(96.266,93.98) U2_LV4.5@96.266,94.96 ; v3(116.249,93.553) U5_LV1.5@117.229,93.553 ; C28_LV1.2@117.263,92.147 U5_LV1.5@117.263,93.587 ; v3(150.165,93.581) U5_LV3.5@151.145,93.581 ; C28_LV3.2@151.179,92.175 U5_LV3.5@151.179,93.615 ; v3(199.136,93.98) 199.136,94.96 U2_LV2.5@199.102,94.994 C8_LV2.2@200.542,94.994 ; C8_LV2.2@200.546,94.998 209.548,94.998 221.058,83.488 C3.2@221.058,78.55 U1.1@222.644,78.55 ; v1(225.245,65.585) 223.225,67.605 U2.1@222.624,67.605 C2.2@221.038,67.605 v1(221.039,69.579) 225.777,69.579 v1(226.048,69.85)
  Component Side w0.635: RLED1.1@34.62,97.344 38.368,101.092 58.03,101.092 ; v1(43.242,86.168) 43.242,86.304 58.03,101.092 ; D5V.1@45.898,60.706 48.26,60.706 50.292,62.738 v1(50.292,65.278) 50.684,65.278 v1(60.338,74.932) ; v1(65.532,92.964) 65.532,95.758 60.198,101.092 v1(59.182,101.092) 58.03,101.092
  Bottom Layer w0.254: AC3.2@44.958,86.168 45.373,86.168 45.874,86.669 U3.61@46.799,86.669 ; U3.80@50.372,95.242 50.372,96.936 51.042,97.606 R_pu2.1@51.042,98.298 ; U3.31@57.872,80.142 57.872,79.014 58.94,77.946 R_pu5.2@58.94,77.724 58.94,76.466 v1@60.464,74.942 ; U3.10@61.922,89.192 63.362,89.192 AC4.2@63.77,89.6
  Bottom Layer w0.305: v1(43.242,86.168) AC3.2@44.704,86.168 ; v1@60.464,74.942 66.802,81.28 66.802,91.694 v1(65.532,92.964) ; v1(67.056,61.976) 67.056,61.722 v1(71.628,57.15) ; v1(106.68,57.15) 125.222,57.15 127,55.372 v3(137.414,55.372)
  Bottom Layer w0.5: v3(96.266,93.98) v3(199.136,93.98) ; v1(221.039,69.579) 222.504,71.044 222.504,77.293 221.12,78.677 v1(221.12,80.328)
  Bottom Layer w0.508: R_pu2.1@51.042,98.298 55.88,98.298 58.674,101.092 v1(59.182,101.092) ; U3.100@60.476,95.242 61.23,94.488 AC5.2@65.594,94.488 65.594,93.026 v1(65.532,92.964) ; AC4.2@63.77,89.6 63.77,91.202 v1(65.532,92.964) ; v3(96.266,93.98) 95.25,92.964 v1(65.532,92.964)
  Bottom Layer w0.635: v1(59.182,101.092) 59.182,102.108 ; v1(225.245,65.585) RADRS1.1@227.624,65.585 228.199,65.585 228.642,66.028 RADRS0.1@229.108,66.028 ; v1(226.048,69.85) RADRS3.1@227.33,71.132 228.046,71.132 228.53,71.616 RADRS2.1@228.854,71.616
  other v1: 47.244,65.278 48.768,65.278
  other v3: 127.474,94.014 158.208,94.014
+5VA: C3_a_LV1.2 C3_b_LV1.2 C16.1 D1.2 D11_LV1.2 D12_LV1.1 L4.2 R_L4.1 | length 116.9
  Component Side w0.3: v1(104.14,30.226) 128.778,30.226 131.572,33.02 v1(131.572,35.306)
  Bottom Layer w0.3: D1.2@24.67,26.924 27.972,30.226 v1(104.14,30.226)
  Bottom Layer w0.75: L4.2@193.638,21.59 193.638,19.48 R_L4.1@195.846,17.272
  other v1: 128.524,35.306 130.048,35.306 127,35.814 133.096,35.814 134.874,35.814 127,37.338 133.096,37.338 134.874,37.338 127,38.862 133.096,38.862 134.874,38.862 127,40.386 133.096,40.386 134.874,40.386
+5VA_FILTERED: C17.1 C18.1 C19.1 J1.26 J1.27 J1.58 J1.59 L4.1 R_L4.2 | length 15
  Component Side w2: J1.58@232.41,33.33 J1.59@232.41,30.79 J1.27@237.49,30.79 J1.26@237.49,33.33
  Bottom Layer w0.75: R_L4.2@197.346,17.272 198.538,18.464 L4.1@198.538,21.59
+5VB: C3_a_LV3.2 C3_b_LV3.2 C4.2 D3.2 D11_LV3.2 D12_LV3.1 L1.2 R_L1.2 | length 150.1
  Component Side w0.3: D3.2@24.67,39.624 66.04,39.624 73.66,32.004 v1(74.422,32.004) ; v1(106.934,28.956) v1(139.7,28.956)
  Component Side w0.75: L1.2@193.638,35.052 193.638,32.942 R_L1.2@195.846,30.734
  Bottom Layer w0.3: v1(74.422,32.004) 75.215,31.211 104.548,31.211 106.803,28.956 v1(106.934,28.956) ; v1(139.7,28.956) 156.062,28.956 v1(162.44,35.334)
  other v1: 163.964,35.334 165.488,35.334 160.916,35.842 167.012,35.842 168.79,35.842 160.916,37.366 167.012,37.366 168.79,37.366 160.916,38.89 167.012,38.89 168.79,38.89 160.916,40.414 167.012,40.414 168.79,40.414
+5VB_FILTERED: C5.2 C6.2 C7.2 J1.20 J1.21 J1.52 J1.53 L1.1 R_L1.1 | length 15
  Component Side w0.75: R_L1.1@197.346,30.734 198.538,31.926 L1.1@198.538,35.052
  Bottom Layer w2: J1.53@232.41,46.03 J1.52@232.41,48.57 J1.20@237.49,48.57 J1.21@237.49,46.03
+5VGNDA: C3_a_LV1.1 C3_b_LV1.1 C16.2 C17.2 C18.2 C19.2 C30.2 D12_LV1.2 J1.28 J1.29 J1.60 J1.61 R_LED1.2 T1_LV1.7 T1_LV1.8 T1_LV1.9 | length 88.9
  Component Side w2: J1.61@232.41,25.71 J1.60@232.41,28.25 J1.28@237.49,28.25 J1.29@237.49,25.71
  Bottom Layer w0.3: R_LED1.2@31.484,24.384 110.236,24.384
  other v1: 112.268,35.052 114.046,35.052 112.268,36.83 114.046,36.83 112.268,38.608 114.046,38.608 111.76,40.132 113.538,40.132 115.316,40.132 117.094,40.132 118.872,40.132 120.65,40.132 112.522,41.656 114.3,41.656 116.078,41.656 117.856,41.656 119.634,41.656 111.506,43.18 113.284,43.18 115.062,43.18 116.84,43.18 118.618,43.18 120.396,43.18 122.174,43.18
+5VGNDB: C3_a_LV3.1 C3_b_LV3.1 C4.1 C5.1 C6.1 C7.1 C32.2 D12_LV3.2 J1.22 J1.23 J1.54 J1.55 R_LED3.2 T1_LV3.7 T1_LV3.8 T1_LV3.9 | length 142.9
  Component Side w0.3: R_LED3.2@29.96,35.56 24.892,35.56 23.114,33.782 23.114,30.226 24.638,28.702 39.116,28.702 v1(40.386,27.432) ; v1(105.664,27.432) 143.51,27.432
  Bottom Layer w0.3: v1(40.386,27.432) v1(105.664,27.432)
  Bottom Layer w2: J1.55@232.41,40.95 J1.54@232.41,43.49 J1.22@237.49,43.49 J1.23@237.49,40.95
  other v1: 146.184,35.08 147.962,35.08 146.184,36.858 147.962,36.858 146.184,38.636 147.962,38.636 145.676,40.16 147.454,40.16 149.232,40.16 151.01,40.16 152.788,40.16 154.566,40.16 146.438,41.684 148.216,41.684 149.994,41.684 151.772,41.684 153.55,41.684 145.422,43.208 147.2,43.208 148.978,43.208 150.756,43.208 152.534,43.208 154.312,43.208 156.09,43.208
+5VRAW: F3.1 J1.2 J1.34 | length 178.4
  Bottom Layer w1.27: F3.1@63.314,104.394 64.33,103.378 223.322,103.378 J1.34@232.41,94.29 J1.2@237.49,94.29
-5VA: C8.1 C9_LV4.1 C10_LV4.1 D6_LV4.2 L2.2 R_L2.2 R_LED2.2 T2_LV4.9 T2_LV4.10 | length 51.5
  Component Side w0.3: R_LED2.2@30.976,30.48 76.454,30.48
  Component Side w0.75: L2.2@193.638,14.732 193.802,14.896 193.802,17.006 195.846,19.05 R_L2.2@195.846,19.812
-5VA_FILTERED: C9.1 C10.1 C11.1 J1.31 J1.63 L2.1 R_L2.1 | length 40.5
  Component Side w0.75: R_L2.1@197.346,19.812 197.346,19.05 198.628,17.768 198.628,14.822 L2.1@198.538,14.732
  Component Side w2: 209.296,16.764 226.822,16.764 230.688,20.63 J1.63@232.41,20.63 J1.31@237.49,20.63
  Bottom Layer w2: J1.63@232.41,20.63 J1.31@237.49,20.63
-5VB: C9_LV2.1 C10_LV2.1 C12.2 D6_LV2.2 L3.2 R_L3.1 R_LED4.2 T2_LV2.9 T2_LV2.10 | length 162.7
  Component Side w0.3: R_LED4.2@33.516,43.18 R_LED4.2@33.262,43.434 54.61,43.434 69.85,58.674 105.481,58.674 108.529,61.722 171.196,61.722 179.26,53.658 v1(179.464,53.658)
  Bottom Layer w0.75: L3.2@193.638,28.194 193.802,28.358 193.802,30.468 R_L3.1@195.846,32.512
  other v1: 179.464,44.514 180.848,45.466 179.464,46.292 180.848,47.244 179.464,48.07 180.848,49.022 179.464,50.102 180.848,51.054 179.464,51.88 180.848,52.832
-5VB_FILTERED: C13.2 C14.2 C15.2 J1.25 J1.57 L3.1 R_L3.2 | length 40.9
  Component Side w2: J1.57@232.41,35.87 J1.25@237.49,35.87
  Bottom Layer w0.75: R_L3.2@197.346,32.512 198.538,31.32 L3.1@198.538,28.194
  Bottom Layer w2: 209.55,28.448 212.852,28.448 220.274,35.87 J1.57@232.41,35.87 J1.25@237.49,35.87
-5VGNDA: C8.2 C9.2 C9_LV4.2 C10.2 C10_LV4.2 C11.2 C31.2 D2.2 D6_LV4.1 D7_LV4.2 J1.30 J1.62 | length 109.8
  Component Side w2: 209.804,23.17 J1.62@232.41,23.17 J1.30@237.49,23.17
  Bottom Layer w0.3: D2.2@24.67,33.274 87.96,33.274 97.676,42.99
  Bottom Layer w2: J1.62@232.41,23.17 J1.30@237.49,23.17
  other v1: 89.916,42.672 91.44,42.672 93.218,42.672 94.996,42.672 96.774,42.672 98.298,42.672 99.822,42.672 101.346,42.672 88.392,44.196 89.916,44.196 91.44,44.196 98.298,44.196 99.822,44.196 101.346,44.196 98.298,45.72 99.822,45.72 101.346,45.72 89.916,47.752 91.44,47.752
-5VGNDB: C9_LV2.2 C10_LV2.2 C12.1 C13.1 C14.1 C15.1 C33.2 D4.2 D6_LV2.1 D7_LV2.2 J1.24 J1.56 | length 220.7
  Component Side w0.3: D4.2@24.67,45.974 26.194,44.45 53.594,44.45 68.58,59.436 105.41,59.436 108.712,62.738 171.958,62.738 175.514,59.182 188.418,59.182 190.64,56.96 190.64,49.26 C9_LV2.2@189.704,48.324
  Component Side w2: J1.56@232.41,38.41 J1.24@237.49,38.41
  Bottom Layer w2: 208.026,37.084 209.55,37.084 210.876,38.41 J1.56@232.41,38.41 J1.24@237.49,38.41
  other v1: 192.532,42.926 194.056,42.926 195.58,42.926 197.104,42.926 198.628,42.926 200.152,42.926 201.676,42.926 203.2,42.926 204.724,42.926 201.676,44.45 203.2,44.45 204.724,44.45 201.676,45.974 203.2,45.974 204.724,45.974 191.262,46.99 192.786,46.99 194.31,46.99 192.786,48.514 194.31,48.514
A0: R5_LV4.2 U2_LV4.1 U3.96 | length 40
  Component Side w0.3: R5_LV4.2@92.584,95.314 92.904,94.994 U2_LV4.1@93.532,94.994 v1@93.532,96.714
  Bottom Layer w0.3: U3.96@58.372,95.242 58.372,96.472 58.372,96.671 59.261,97.56 92.686,97.56 v1(93.472,96.774)
A1: R10_LV3.2 U3.95 U5_LV3.1 | length 98.5
  Component Side w0.5: v1(151.13,97.79) 151.184,97.736 U5_LV3.1@151.184,96.374 ; U5_LV3.1@151.179,96.315 R10_LV3.2@152.015,96.315
  Bottom Layer w0.3: U3.95@57.872,95.242 57.872,96.988 58.944,98.06 114.3,98.06 115.332,97.028 150.368,97.028 v1(151.13,97.79)
A2: R10_LV1.2 U3.94 U5_LV1.1 | length 65.1
  Component Side w0.5: v1(117.094,98.044) 117.268,97.87 U5_LV1.1@117.268,96.346 ; U5_LV1.1@117.263,96.287 R10_LV1.2@118.099,96.287
  Bottom Layer w0.3: U3.94@57.372,95.242 57.372,97.195 58.737,98.56 116.578,98.56 v1(117.094,98.044)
